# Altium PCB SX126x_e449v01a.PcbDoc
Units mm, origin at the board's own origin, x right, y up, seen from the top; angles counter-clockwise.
Board outline 89 x 58 mm, 4 copper layers (Top Layer, MidLayer1, MidLayer2, Bottom Layer), stack 0.986 mm thick; 79 components, 51 nets, 222 pads, 1241 vias.
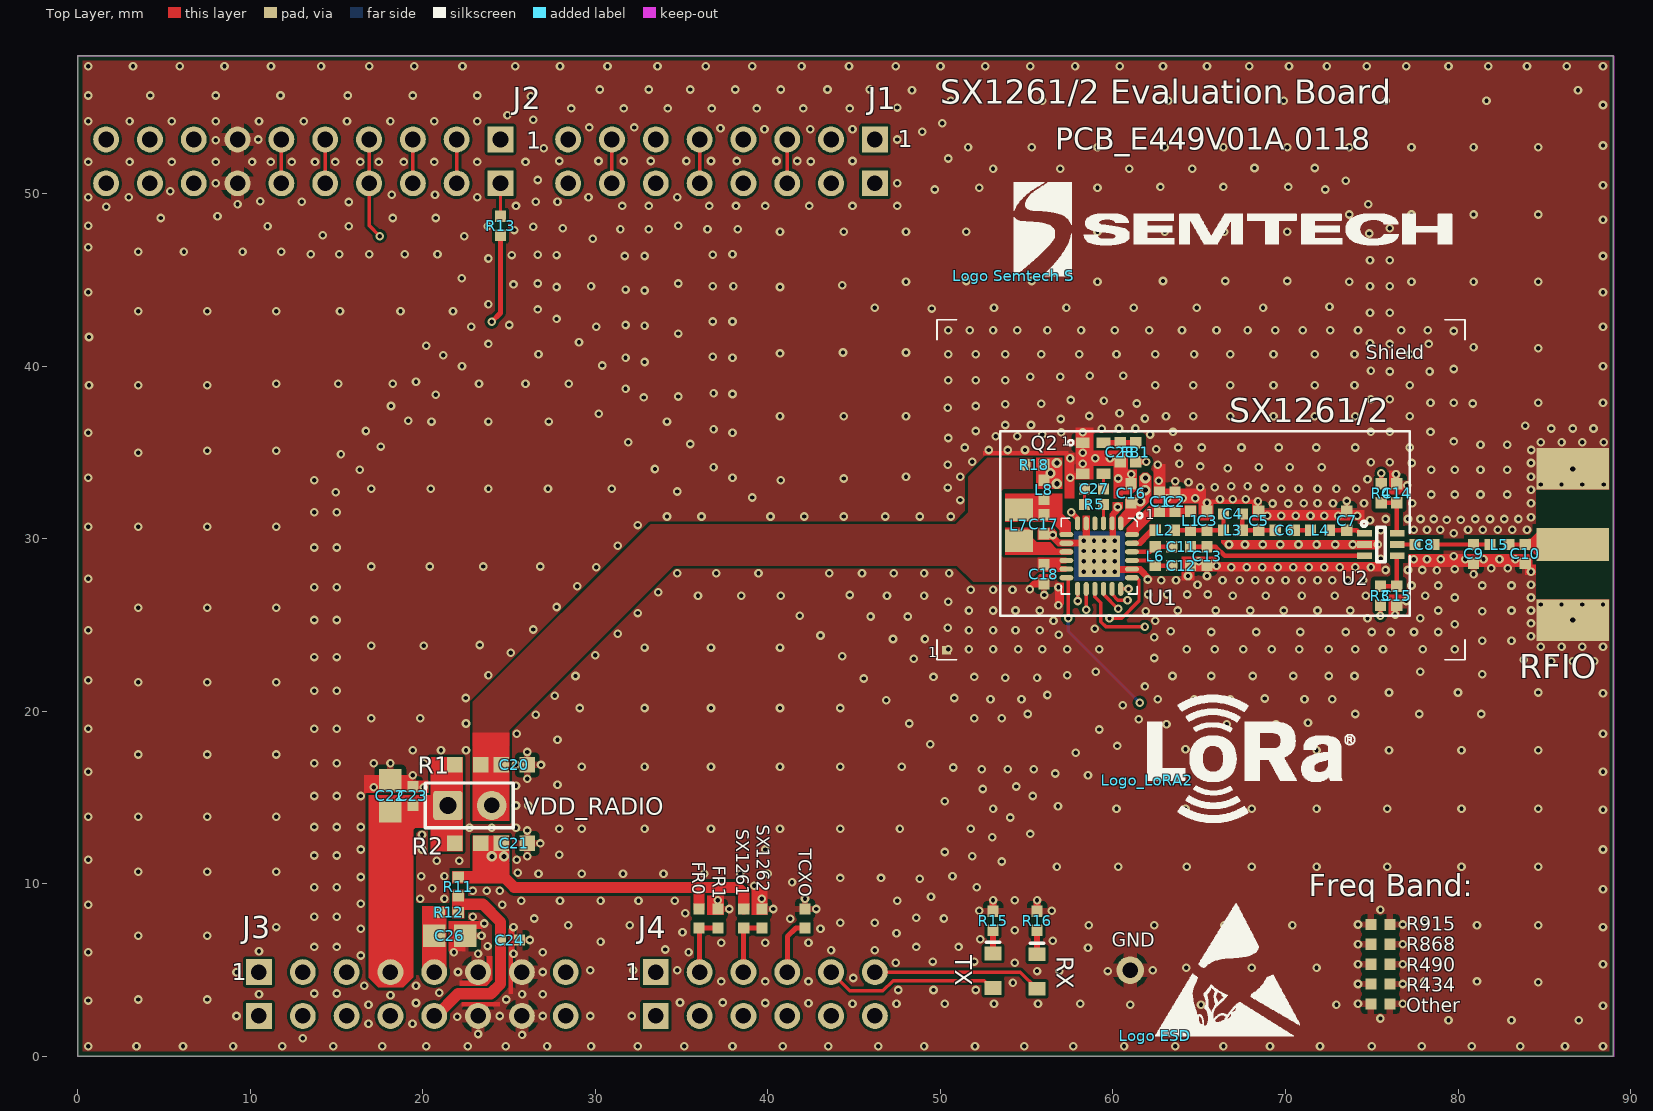
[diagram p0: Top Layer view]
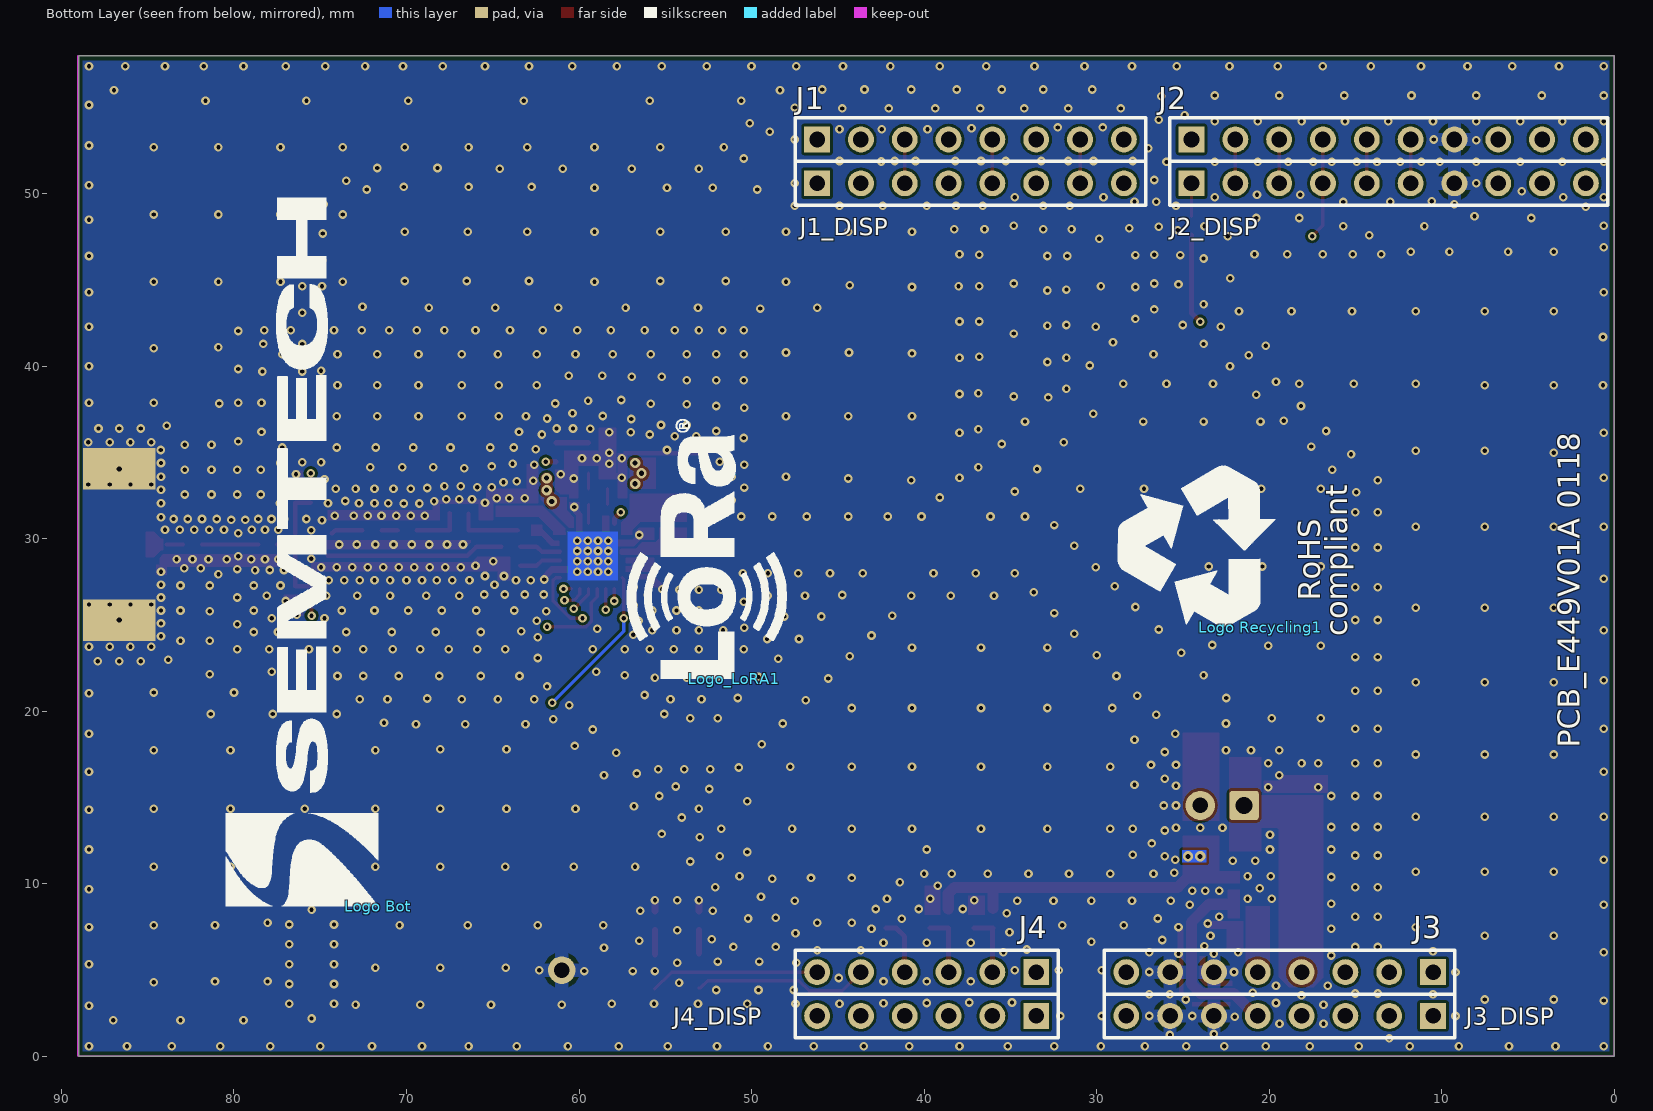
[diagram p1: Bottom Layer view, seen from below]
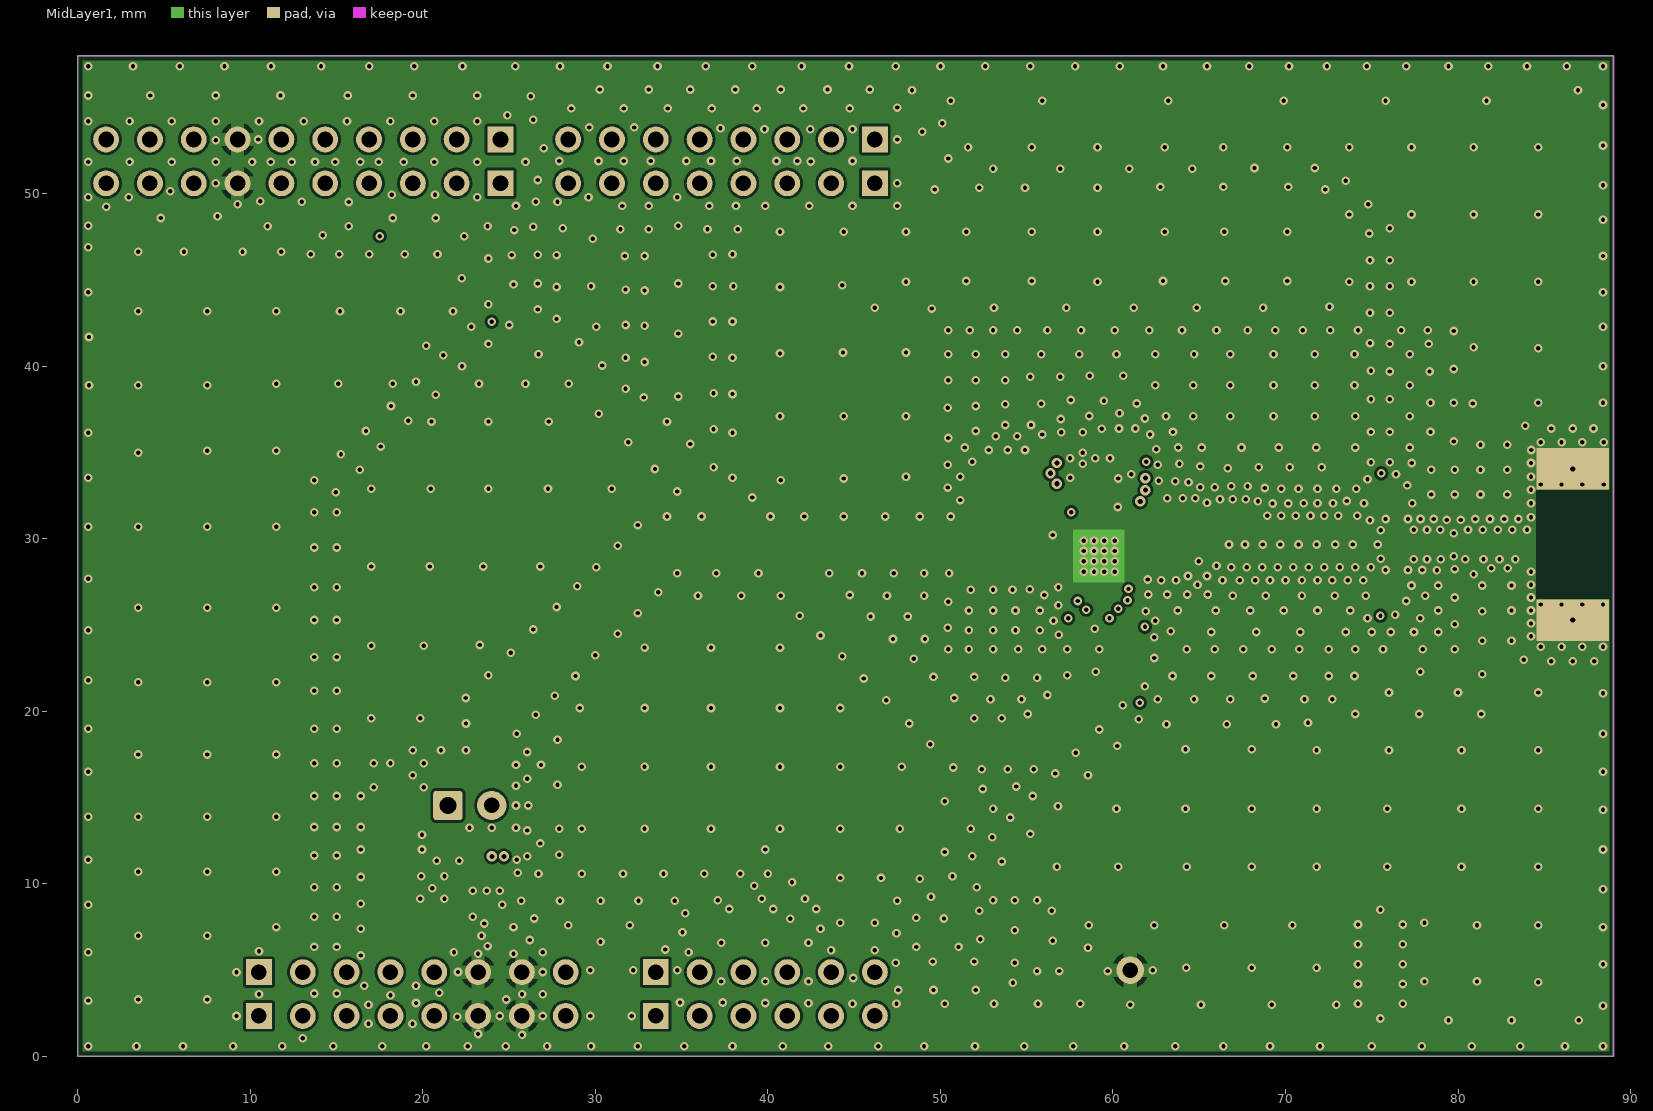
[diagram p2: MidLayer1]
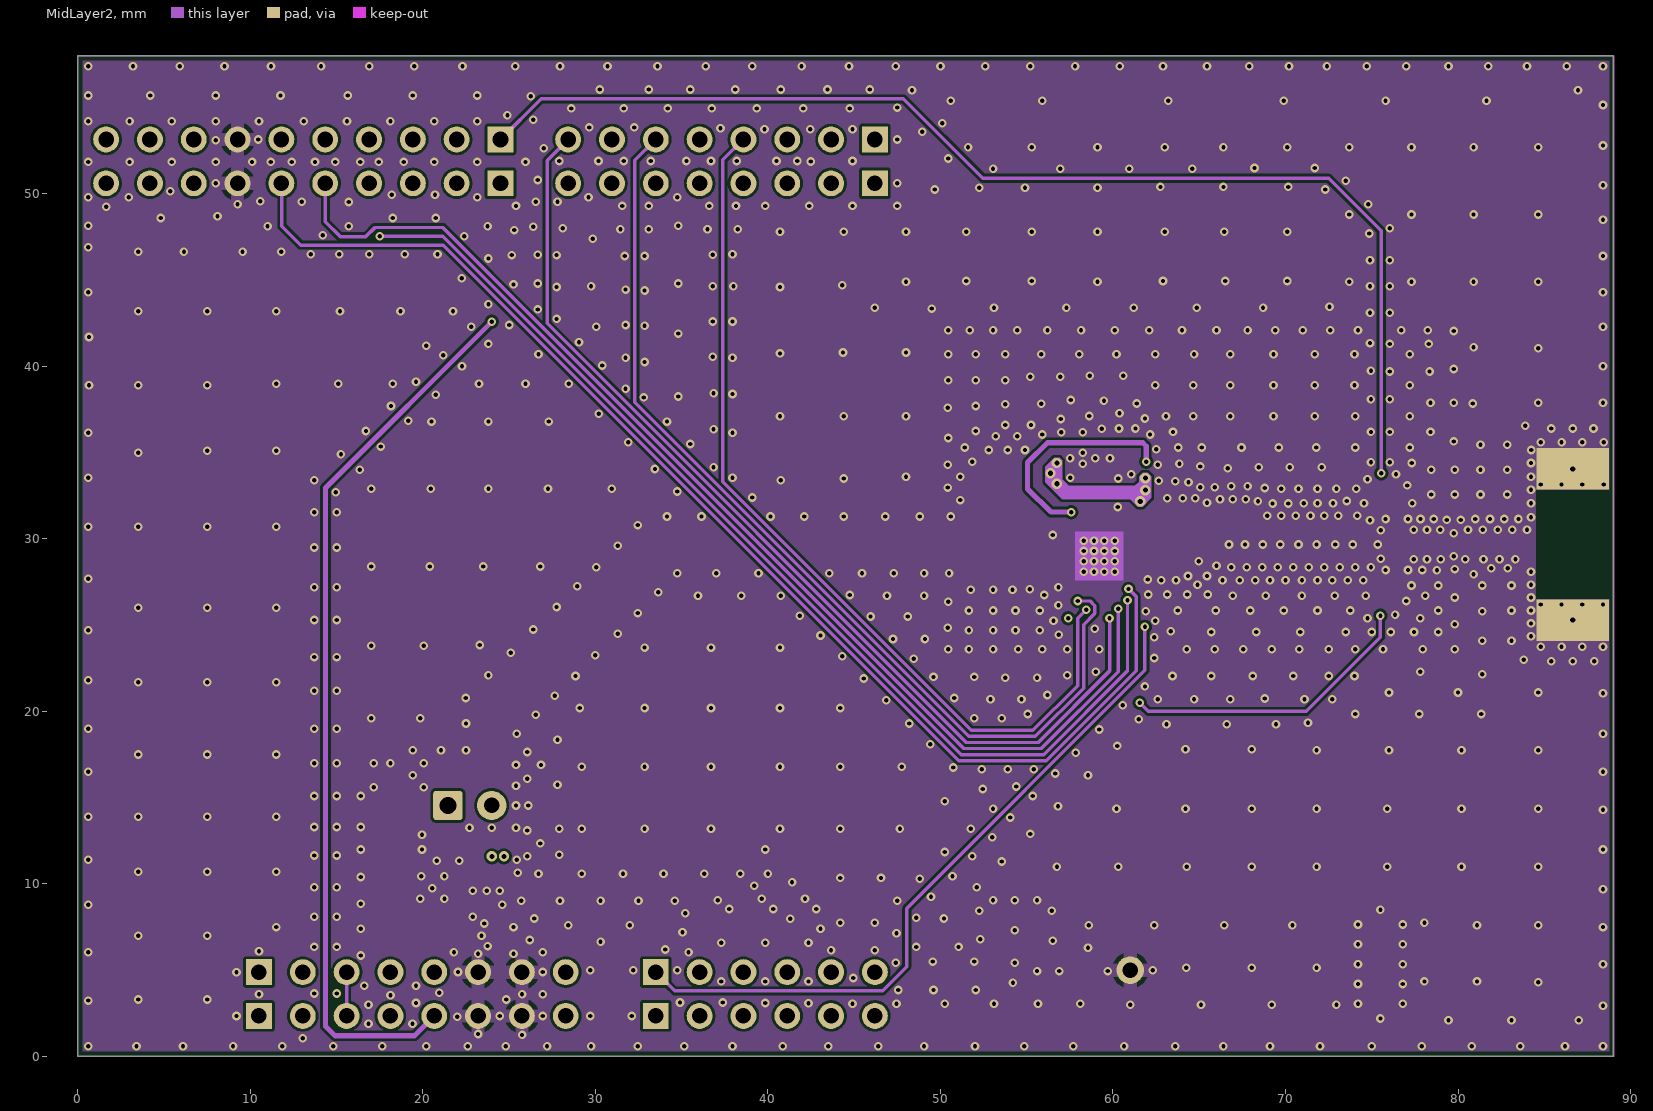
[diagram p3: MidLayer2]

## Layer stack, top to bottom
Top Solder: solder mask 0.0102, Solder Resist, Dk 3.5
Top Layer: signal copper 0.035
Dielectric1: core 0.15, FR-4, Dk 4.4
MidLayer1: signal copper 0.018
Dielectric3: prepreg 0.58, FR-4, Dk 4.4
MidLayer2: signal copper 0.018
Dielectric2: core 0.15, FR-4, Dk 4.4
Bottom Layer: signal copper 0.035
Bottom Solder: solder mask 0.0102, Solder Resist, Dk 3.5

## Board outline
0,0 0,58 89,58 89,0

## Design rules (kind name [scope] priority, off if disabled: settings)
Clearance Clearance_RF_GND [InNet('GND') And OnLayer('Top Layer') And (InPoly) vs InNet('NetL*') or InNet('NetC*') or InNet('NetU*')] p1: gap=0.25 ignorepadtopadclearanceinfootprint=FALSE except(0: Arc-Hole Track-Hole SMDPad-Hole THPad-Hole Via-Hole Fill-Hole Poly-Hole Region-Hole Text-Hole)
Clearance Clearance_GND_Keepout [InNet('GND') vs OnLayer('Keep-Out Layer')] p2: gap=0.15 ignorepadtopadclearanceinfootprint=FALSE except(0: Arc-Hole Track-Hole SMDPad-Hole THPad-Hole Via-Hole Fill-Hole Poly-Hole Region-Hole Text-Hole)
Clearance Clearance_GND [InNet('GND')] p3: gap=0.15 ignorepadtopadclearanceinfootprint=FALSE except(0: Arc-Hole Track-Hole SMDPad-Hole THPad-Hole Via-Hole Fill-Hole Poly-Hole Region-Hole Text-Hole)
Clearance [All] p4: gap=0.15 ignorepadtopadclearanceinfootprint=FALSE except(0: Arc-Hole Track-Hole SMDPad-Hole THPad-Hole Via-Hole Fill-Hole Poly-Hole Region-Hole Text-Hole)
ComponentClearance ComponentClearance_SMA_RFIO [InComponent('RFIO')] p1: gap=0.1 collisioncheckmode=3 verticalgap=0.1 showdistances=FALSE
ComponentClearance [All] p2: gap=0.2 collisioncheckmode=3 verticalgap=0.3 showdistances=FALSE
HoleSize [All] p1: absolutevalues=TRUE maxlimit=3.6 minlimit=0.25 maxpercent=80.000 minpercent=20.000
HoleToHoleClearance [All] p1: gap=0.2 allowstackedmicrovias=TRUE
MinimumSolderMaskSliver [All] p1: minsoldermaskwidth=0.04
PlaneClearance [All] p1: clearance=0.2
PlaneConnect [All] p1: planeconnectstyle=Direct reliefexpansion=0.508 reliefentries=4 reliefconductorwidth=0.254 reliefairgap=0.254
PolygonConnect "PolygonConnect SMD" [InNet('GND') vs HasFootprint('rlc_603_smd') or HasFootprint('rlc_402_smd') or hasFootprint('rlc_805_smd')  or hasFootprint('SOT353-5') or hasFootprint('VQFN24_4X4MM')   or hasFootprint('TCXO 2.0x1.6mm')  or HasFootprint('ND2016DA')  or HasFootprint('DFN6_3X3mm')   or HasFootprint('ODFN6_1.65X1.65mm')] p1: connectstyle=Relief reliefconductorwidth=0.4 reliefentries=4 polygonreliefangle="90 Angle" airgapwidth=0.254
PolygonConnect PolygonConnect_comp_diverse [InNet('GND') or  InNet('VDD_MBED') or  InNet('VDD_DISPLAY')  or  InNet('VDD_3V3')  or  InNet('VDD_RADIO')  or  InNet('VUSB') vs HasFootprint('LGM676 LED') or  HasFootprint('BRIDGE_254MM') or  HasFootprint('pin_0.9mm') or HasFootprint('SMA_STRAIGHT')  or  HasFootprint('HDR2X8')   or  HasFootprint('HDR2X6')  or  HasFootprint('HDR1X10') or  HasFootprint('vqfn20_3x3mm') or  HasFootprint('HDR1X9') or  HasFootprint('HDR1X8')  or  HasFootprint('HDR1X6') or  HasFootprint('HDR1X4')] p2: connectstyle=Relief reliefconductorwidth=0.8 reliefentries=4 polygonreliefangle="90 Angle" airgapwidth=0.254
PolygonConnect PolygonConnect_all [All] p3: connectstyle=Direct reliefconductorwidth=0.6 reliefentries=4 polygonreliefangle="90 Angle" airgapwidth=0.254
RoomDefinition SX126x_e449v01a [InComponentClass('SX126x_e449v01a')] p1: confinementstyle=ConfineOut formatcopy=TRUE lockcomponents=FALSE outline 13.5,81.35 13.45,81.4 13.45,124.35 67.45,124.35 67.3,124.2 67.3,81.35
RoutingVias [All] p1: holewidth=0.3 width=0.6 viastyle="Through Hole" minholewidth=0.25 minwidth=0.5 maxholewidth=0.4 maxwidth=0.8
SilkToSilkClearance [All] p1: silktosilkclearance=0.05
SilkToSolderMaskClearance SilkscreenOverComponentPads [IsPad] p1: minsilkscreentomaskgap=0.05 clearancetoexposedcopper=TRUE
SolderMaskExpansion [All] p1: expansion=0.05
Width "Width GND" [InNet('GND')] p1: maxlimit=3 minlimit=0.2 preferedwidth=0.4
Width Width_VCC [InNet('VDD') or  InNet('VDISPLAY') or  InNet('VDD_MBED')  or  InNet('VUSB')  or  InNet('VDD_3V3')] p2: maxlimit=2 minlimit=0.2 preferedwidth=0.8
Width "Width All" [All] p3: maxlimit=2 minlimit=0.15 preferedwidth=0.2
22 further rules are at their usual default settings.

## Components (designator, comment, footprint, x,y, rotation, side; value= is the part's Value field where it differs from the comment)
C1 "Cap" RLC_402_SMD 62.7,32.15 r270 top value=NC
C2 "Cap" RLC_402_SMD 63.6,32.15 r270 top value=NC
C3 "Cap" RLC_402_SMD 65.45,31.05 r270 top value=NC
C4 "Cap" RLC_402_SMD 66.95,31.45 r180 top value=NC
C5 "Cap" RLC_402_SMD 68.45,31.05 r270 top value=NC
C6 "Cap" RLC_402_SMD 69.95,30.5 r180 top value=NC
C7 "Cap" RLC_402_SMD 73.55,31.05 r270 top value=NC
C8 "Cap" RLC_402_SMD 78.05,29.675 r180 top value=NC
C9 "Cap" RLC_402_SMD 80.9,29.125 r90 top value=NC
C10 "Cap" RLC_402_SMD 83.9,29.125 r90 top value=NC
C11 "Cap" RLC_402_SMD 63.95,29.55 r180 top value=NC
C12 "Cap" RLC_402_SMD 63.95,28.45 r180 top value=NC
C13 "Cap" RLC_402_SMD 65.45,29 r90 top value=NC
C14 "Cap" RLC_402_SMD 76.45,32.65 r90 top value=1nF
C15 "Cap" RLC_402_SMD 76.45,26.7 r270 top value=1nF
C16 "Cap" RLC_402_SMD 61.05,32.65 r270 top value=1uF
C17 "Cap" RLC_402_SMD 56,30.85 r90 top value=470nF
C18 "Cap" RLC_402_SMD 56,27.95 r90 top value=100nF
C20 "Cap" rlc_603_smd 25.3,16.9 r180 top value=1uF
C21 "Cap" rlc_603_smd 25.3,12.35 r180 top value=1uF
C22 "Cap" rlc_805_smd 18.12,15.1 r270 top value=10uF
C23 "Cap" RLC_402_SMD 19.42,15.1 r270 top value=100nF
C24 "Cap" RLC_402_SMD 25.05,6.75 r180 top value=1uF
C26 "Cap" rlc_805_smd 21.55,7 r180 top value=10uF
C27 "Cap" RLC_402_SMD 58.9,32.9 r180 top value=15pF
C28 "Cap" RLC_402_SMD 60.425,35.025 r90 top value=100nF
FB1 "Ferrite beads" RLC_402_SMD 61.325,35.025 r90 top value=NC
FR0 "Resistor" RLC_402_SMD 36,8 r270 top value=1k
FR1 "Resistor" RLC_402_SMD 37.1,8 r270 top value=NC
GND "Test Pin" pin_0.9mm 61,5 r90 top
J1 "Header 8" HDR1X8 46.2,53.15 r180 bottom locked
J1_DISP "Header 8" HDR1X8 46.2,50.61 r180 bottom locked
J2 "Header 10" HDR1X10 24.5,53.15 r180 bottom locked
J2_DISP "Header 10" HDR1X10 24.5,50.61 r180 bottom locked
J3 "Header 8" HDR1X8 10.5,4.89 r0 bottom locked
J3_DISP "Header 8" HDR1X8 10.5,2.35 r0 bottom locked
J4 "Header 6" HDR1X6 33.5,4.89 r0 bottom locked
J4_DISP "Header 6" HDR1X6 33.5,2.35 r0 bottom locked
L1 "Inductor" RLC_402_SMD 64.5,31.05 r90 top value=0R
L2 "Inductor" RLC_402_SMD 63,30.5 r0 top value=0R
L3 "Inductor" RLC_402_SMD 66.95,30.5 r0 top value=0R
L4 "Inductor" RLC_402_SMD 72,30.5 r0 top value=0R
L5 "Inductor" RLC_402_SMD 82.4,29.675 r0 top value=0R
L6 "Inductor" RLC_402_SMD 62.45,29 r90 top value=0R
L7 "Inductor" "rlc_805_smd enlarged" 54.55,30.8 r270 top value=15uH
L8 "Inductor" rlc_402_smd 56,32.85 r270 top value=47nH
"Logo Bot" "Logo symbol" logo_semtech_horiz_size4 71.65,8.7 r90 bottom
"Logo ESD" "Logo symbol" "Logo ESD" 62.454,1.2 r0 top
"Logo Recycling1" "Logo symbol" "Logo Recycling1" 20.527,24.87 r90 bottom
"Logo Semtech S" "Logo symbol" logo_semtech_horiz_size3 54.25,45.25 r0 top
Logo_LoRA1 "Logo symbol" "LOGO LORA SIZE4" 51,21.9 r90 bottom
Logo_LoRA2 "Logo symbol" "LOGO LORA SIZE3" 62,16 r0 top
Other "Resistor" RLC_402_SMD 75.5,3.05 r0 top value=NC
Q2 "TCXO" "TCXO 2.0x1.6mm" 58.85,34.675 r270 top value=32.0MHz
R1 "Resistor" rlc_603_smd 22.6,16.9 r180 top value=NC
R2 "Resistor" rlc_603_smd 22.6,12.35 r180 top value=0R
R3 "Resistor" RLC_402_SMD 75.5,26.7 r270 top value=100R
R4 "Resistor" RLC_402_SMD 75.55,32.65 r90 top value=100R
R5 "Resistor" rlc_402_smd 58.9,32 r180 top value=?
R11 "Resistor" RLC_402_SMD 22.05,9.85 r270 top value=NC
R12 "Resistor" RLC_402_SMD 21.5,8.35 r0 top value=0R
R13 "Resistor" RLC_402_SMD 24.5,48.15 r90 top value=10k
R15 "Resistor" RLC_402_SMD 53.05,7.871 r270 top value=330R
R16 "Resistor" RLC_402_SMD 55.6,7.871 r270 top value=330R
R18 "Resistor" rlc_402_smd 55.45,34.3 r180 top value=0R
R434 "Resistor" RLC_402_SMD 75.5,4.2 r0 top value=NC
R490 "Resistor" rlc_402_smd 75.5,5.35 r180 top value=NC
R868 "Resistor" RLC_402_SMD 75.5,6.5 r0 top value=NC
R915 "Resistor" RLC_402_SMD 75.5,7.65 r180 top value=NC
RFIO "SMA" SMA_end_launch_1.0mm_9.52mm 86.65,29.675 r0 top locked
RX "LED" "LGM676 LED" 55.6,4.921 r90 top value=GREEN
Shield "Logo symbol" "BMIS-209-F - Shield - Solder_Mask" 50.35,23.55 r0 top locked
SX1261 "Resistor" rlc_402_smd 38.6,8 r270 top value=NC
SX1262 "Resistor" RLC_402_SMD 39.65,8 r270 top value=10k
TCXO "Resistor" rlc_402_smd 42.15,8 r270 top value=NC
TX "LED" "LGM676 LED" 53.05,4.971 r90 top value=RED
U1 "SX1261/2" VQFN24_4X4MM 59.2,29 r270 top
U2 "PE4259 RF Switch" SC70-6 75.525,29.675 r0 top
VDD_RADIO "Jumper" BRIDGE_254MM 21.45,14.55 r0 top

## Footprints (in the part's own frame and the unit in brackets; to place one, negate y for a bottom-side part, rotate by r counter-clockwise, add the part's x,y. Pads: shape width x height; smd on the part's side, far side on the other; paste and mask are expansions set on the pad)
"BMIS-209-F - Shield - Solder_Mask" [mm] "BMIS-209-F EMI Gasket - modif SolderMask - Standard Surface Mount Shields -  Laird Technologies"
  rect 0.5x0.5 smd paste-1 mask+0.05: 1(0,0)
  Mechanical 15 keep-out lines w1: 0,0 0,18.6 29.5,18.6 29.5,0 0,0
  silkscreen extent -0.55,-0.55 30.05,19.15, body extent -0.3,-0.3 0.3,0.3, height 0.8
BRIDGE_254MM [mm] "Generic Bridge 2.54mm, 2 Leads 0.9mm;"
  rrect20% 1.7x1.7 hole 1 paste+0 mask+0.05: 1(0,0)
  round 1.7 hole 0.9 paste+0 mask+0.05: 2(2.54,0)
  silkscreen extent -1.3,-1.3 3.8,1.3, body extent -1.4,-1.4 3.9,1.4, height 1
HDR1X6 [mm] "Connector; Header; 6 Position"
  rect 1.5x1.5 hole 0.9: 1(0,0)
  round 1.5 hole 0.9: 2(2.54,0) 3(5.08,0) 4(7.62,0) 5(10.16,0) 6(12.7,0)
  silkscreen extent -1.27,-1.27 13.97,1.27, body extent -0.8,-0.8 13.5,0.8
HDR1X8 [mm] "Connector; Header; 8 Position"
  rect 1.5x1.5 hole 0.9: 1(0,0)
  round 1.5 hole 0.9: 2(2.54,0) 3(5.08,0) 4(7.62,0) 5(10.16,0) 6(12.7,0) 7(15.24,0) 8(17.78,0)
  silkscreen extent -1.27,-1.27 19.05,1.27, body extent -0.8,-0.8 18.58,0.8
HDR1X10 [mm] "Connector; Header; 10 Position"
  rect 1.5x1.5 hole 0.9: 1(0,0)
  round 1.5 hole 0.9: 2(2.54,0) 3(5.08,0) 4(7.62,0) 5(10.16,0) 6(12.7,0) 7(15.24,0) 8(17.78,0) 9(20.32,0) 10(22.86,0)
  silkscreen extent -1.27,-1.27 24.13,1.27, body extent -0.8,-0.8 23.66,0.8
"LGM676 LED" [mm] "Chip Diode; Body 2.1 x 1.4 mm (LxW typ)"
  rect 0.8x1 smd mask+0.05: 1(-1,0) 2(1,0)
  silkscreen extent 1.65,-0.4 1.65,0.4, body extent -1.2,-0.7 1.2,0.7, height 12
"Logo ESD" [mm] "Logo ESD"
  silkscreen extent 0,0 8.38,7.67
"LOGO LORA SIZE3" [mm] "Logo LoRa Size3 - Top Overlay - 14.5x8mm - Registered"
  silkscreen extent 0,-2.44 12.03,4.96, body extent 2.3,-0.1 5.25,2.65, height 0.8
"LOGO LORA SIZE4" [mm] "Logo LoRa Size4 - Top Overlay - 18x9.5mm - Registered"
  silkscreen extent 0,-3.05 15.04,6.2
"Logo Recycling1" [mm] "Logo Recycling1"
  silkscreen extent 0.05,-0.88 9.36,8.2
logo_semtech_horiz_size3 [mm] "Logo semtech horizontal - size3 - L"
  silkscreen extent 0,0 25.4,5.41
logo_semtech_horiz_size4 [mm] "Logo semtech horizontal - size4 - XL"
  silkscreen extent 0,0 41.07,8.79
pin_0.9mm [mm] "Generic Pin 0.9mm; 1 Lead"
  round 1.6 hole 0.9 mask+0.05: 1(0,0)
RLC_402_SMD [mm] "Chip SMD component 402; Body 1.0 x 0.5 mm (LxW typ)"
  rect 0.65x0.65 smd mask+0.05: 1(-0.55,0) 2(0.55,0)
  body extent -0.87,-0.33 0.87,0.33, height 0.8
rlc_402_smd [mm] "Chip SMD component 402; Body 1.0 x 0.5 mm (LxW typ)"
  rect 0.65x0.65 smd mask+0.05: 1(-0.55,0) 2(0.55,0)
  body extent -0.87,-0.33 0.87,0.33, height 0.8
rlc_603_smd [mm] "Chip SMD component 603; Body 1.6 x 0.8mm (LxW typ)"
  rect 0.9x0.9 smd paste+0 mask+0.05: 1(-0.75,0) 2(0.75,0)
rlc_805_smd [mm] "Chip SMD component 805; Body 2.0 x 1.25 mm (LxW typ)"
  rect 1.3x1.3 smd mask+0.05: 1(-0.9,0) 2(0.9,0)
"rlc_805_smd enlarged" [mm] "Chip SMD component 805; Body 2.0 x 1.25 mm (LxW typ)"
  rect 1.3x1.6 smd mask+0.05: 1(-0.9,0) 2(0.9,0)
SC70-6 [mm] "SC70 6-Leads, Body 2.0x1.25mm, Pitch 0.65mm"
  rect 0.85x0.4 smd mask+0.05: 1(-0.95,0.65) 2(-0.95,0) 3(-0.95,-0.65) 4(0.95,-0.65) 5(0.95,0) 6(0.95,0.65)
  silkscreen extent -1.12,-1 0.25,1.35, body extent -0.63,-1 0.63,1, height 1.45
SMA_end_launch_1.0mm_9.52mm [mm] "SMA end launch for 1.0mm PCB thickness; 9.52mm"
  rect 4.2x1.905 smd mask+0.05: 1(0,0)
  rect 4.2x2.413 hole 0.3 mask+0.05: 2(0,-4.38) 2(0,4.38)
"TCXO 2.0x1.6mm" [mm] "SMD 2.0x1.6mm for TCXO or VCTCXO"
  rect 0.6x0.8 smd mask+0.05: 1(-0.9,-0.6) 2(0.9,-0.6) 3(0.9,0.6) 4(-0.9,0.6)
  silkscreen extent -1.05,-1.45 -0.75,-1.15, body extent -1,-0.8 1,0.8, height 1
VQFN24_4X4MM [mm] "24 Leads, Body 4.0x4.0mm, Pitch 0.50mm, VQFN24"
  oval 0.8x0.3 smd mask+0.05: 1(-1.9,1.25) 2(-1.9,0.75) 3(-1.9,0.25) 4(-1.9,-0.25) 5(-1.9,-0.75) 6(-1.9,-1.25) 13(1.9,-1.25) 14(1.9,-0.75) 15(1.9,-0.25) 16(1.9,0.25) 17(1.9,0.75) 18(1.9,1.25)
  oval 0.3x0.8 smd mask+0.05: 7(-1.25,-1.9) 8(-0.75,-1.9) 9(-0.25,-1.9) 10(0.25,-1.9) 11(0.75,-1.9) 12(1.25,-1.9) 19(1.25,1.9) 20(0.75,1.9) 21(0.25,1.9) 22(-0.25,1.9) 23(-0.75,1.9) 24(-1.25,1.9)
  rrect5% 2.4x2.4 smd paste-2.5 mask+0.05: 25(0,0)
  Mechanical 15 keep-out lines w0.1: 2.5,-2.5 2.5,2.5 -2.5,2.5 -2.5,-2.5 2.5,-2.5
  silkscreen extent -2.5,-2.2 2.2,2.5, body extent -2,-2 2,2, height 1

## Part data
C1 C2 C3 C4 C5 C6 C7 C8 C9 C10 C11 C12 C13 C14 C15 C16 C17 C18 C20 C21 C22 C23 C24 C26 C27 C28: "Capacitor SMD"
FR0 FR1 Other R1 R2 R3 R4 R5 R11 R12 R13 R15 R16 R18 R434 R490 R868 R915 SX1261 SX1262 TCXO: "Resistor SMD - IEC symbol version"
GND: library part test_pin
J1 J1_DISP J3 J3_DISP: "Header, 8-Pin"
J2 J2_DISP: "Header, 10-Pin"
J4 J4_DISP: "Header, 6-Pin"
L1 L2 L3 L4 L5 L6 L7 L8: "Inductor SMD"
"Logo Bot" "Logo ESD" "Logo Recycling1" "Logo Semtech S" Logo_LoRA1 Logo_LoRA2: library part Logo, "Schematic symbol for Logo"
RFIO: "SMA Straight Connector"
Shield: library part Shield, "Shield - EMI Gasket - Standard Surface Mount Shields"
U1: library part SX126x, "SX1261/2 - Ultra low power RF transceiver"
U2: "PE4259 Peregrine RF Switch"
VDD_RADIO: "Jumper Wire"

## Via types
v1: diameter 0.5, hole 0.25, Top Layer to Bottom Layer, tented both sides, 1217 vias
v2: diameter 0.5, hole 0.25, Top Layer to Bottom Layer, tented top, 16 vias
v3: diameter 0.6, hole 0.3, Top Layer to Bottom Layer, tented both sides, 8 vias

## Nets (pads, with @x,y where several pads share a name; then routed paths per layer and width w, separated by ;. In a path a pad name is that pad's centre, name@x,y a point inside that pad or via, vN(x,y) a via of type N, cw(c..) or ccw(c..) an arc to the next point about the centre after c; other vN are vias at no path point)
ANT_SW: J2.1 R4.2 | length 69.8
  Top Layer w0.25: R4.2 v1(75.55,33.8)
  MidLayer2 w0.2: J2.1 26.85,55.5 47.85,55.5 52.45,50.9 72.5,50.9 75.55,47.85 v1(75.55,33.8)
BUSY: J1.4 U1.14 | length 53.7
  Top Layer w0.2: v1(58.45,25.9) U1.14
  MidLayer2 w0.2: J1.4@38.575,53.15 37.39,51.965 37.39,33.305 51.795,18.9 55.35,18.9 57.95,21.5 57.95,25.4 v1(58.45,25.9)
DIO1: J1.6 U1.13 | length 57.8
  Top Layer w0.2: v1(57.95,26.4) U1.13
  MidLayer2 w0.2: J1.6 32.286,51.936 32.286,37.914 51.65,18.55 55.5,18.55 58.3,21.35 58.3,25.025 58.95,25.675 58.95,26.125 58.675,26.4 v1(57.95,26.4)
DIO2: R3.2 U1.12 | length 26.8
  Top Layer w0.2: v1(57.4,25.4) 57.4,27.65 U1.12@57.5,27.75
  Top Layer w0.25: v1(75.5,25.55) R3.2
  MidLayer2 w0.2: v1(61.55,20.5) 62.05,20 71.199,20 75.5,24.301 v1(75.5,25.55)
  Bottom Layer w0.2: v1(57.4,25.4) 57.399,24.651 v1(61.55,20.5)
DIO3: FB1.1 U1.6 | length 14.3
  Top Layer w0.3: v1(57.575,31.55) 57.95,31.175 U1.6 ; FB1.1 v1(61.925,34.475)
  MidLayer2 w0.3: v1(57.575,31.55) 56.4,31.55 55.05,32.9 55.05,34.425 56.2,35.575 61.725,35.575 61.925,35.375 v1(61.925,34.475)
DISP_RESET: J3.3 J3_DISP.3 | length 2.5
  Top Layer w0.3: J3.3@15.58,4.87 J3.3@15.6,4.89
  MidLayer2 w0.2: J3_DISP.3 J3.3@15.58,4.87
F_CS: J1.7 J1_DISP.7 | length 2.6
  Top Layer w0.2: J1.7@30.95,53.175 30.96,53.165 J1.7 J1_DISP.7
GND: C1.1 C2.1 C3.1 C5.1 C7.1 C9.1 C10.1 C12.1 C13.1 C14.2 C15.2 C16.1 C17.1 C18.1 C20.1 C21.1 C22.1 C23.1 C24.1 C26.1 C28.1 FR1.1 GND.1 J2.7 J2_DISP.7 J3.6 J3.7 J3_DISP.6 J3_DISP.7 Other.1 Other.2 Q2.1 Q2.2 R15.1 R16.1 R434.1 R434.2 R490.1 R490.2 R868.1 R868.2 R915.1 R915.2 RFIO.2 Shield.1 SX1262.1 TCXO.1 U1.2 U1.5 U1.8 U1.20 U1.25 U2.2 | length 5.3
  Top Layer w0.3: U1.8 U1.25@58.3,29.75 ; U1.25@58.45,29.85 U1.5 ; U1.25@59.95,29.9 U1.2 ; U1.25@60.1,28.2 60.15,28.25 U1.20 ; C16.1@61.012,33.2 C16.1
  Top Layer w0.4: R15.1 v1@53.05,9.021 ; R16.1 v1(55.6,9.05)
  other v1: 0.6,0.6 3.4,0.6 6.1,0.6 9,0.6 11.85,0.6 14.8,0.6 17.65,0.6 20.2,0.6 22.6,0.6 24.8,0.6 27.2,0.6 29.75,0.6 32.45,0.6 35.15,0.6 37.95,0.6 40.85,0.6 43.5,0.6 46.4,0.6 49.05,0.6 52,0.6 54.85,0.6 57.7,0.6 60.643,0.6 63.6,0.6 66.4,0.6 69.1,0.6 72,0.6 75,0.6 77.9,0.6 80.8,0.6 83.6,0.6 86.2,0.6 88.4,0.6 13.04,1.05 25.75,1.25 23.2,1.3 16.85,1.9 19.4,1.9 79.45,2.1 83.1,2.1 87,2.1 75.5,2.2 22,2.3 9.2,2.35 24.45,2.35 26.95,2.35 29.7,2.35 32.1,2.35 88.4,2.938 16.85,3 61,3 65.1,3 69.2,3 72.95,3 44.9,3.05 47.45,3.05 50.25,3.05 53.1,3.05 55.65,3.05 58.1,3.05 74.2,3.05 76.8,3.05 19.6,3.1 39.85,3.1 42.35,3.088 34.9,3.13 37.39,3.13 0.6,3.241 3.5,3.3 7.5,3.3 24.829,3.3 18.125,3.55 10.5,3.6 25.75,3.6 26.95,3.6 13.7,3.65 15,3.65 20.95,3.7 47.55,3.85 49.6,3.85 52.05,3.85 16.6,4.1 19.6,4.1 74.2,4.2 76.8,4.2 54.2,4.279 84.65,4.3 37.3,4.35 39.85,4.35 42.35,4.35 78.05,4.35 81.1,4.35 44.95,4.55 9.2,4.89 22.035,4.9 26.95,4.9 55.6,4.95 56.886,4.95 59.7,4.95 29.7,5 32.2,5 34.75,5 62.3,5 64.25,5.15 68.05,5.15 71.8,5.15 88.4,5.338 74.2,5.35 76.8,5.35 47.4,5.435 54.3,5.435 49.55,5.5 51.95,5.5 16.4,5.85 23.2,5.95 25.25,5.95 0.6,6.05 21.8,6.05 26.95,6.05 35.4,6.05 10.5,6.1 43.66,6.15 46.2,6.15 34.046,6.2 58.55,6.3 13.7,6.35 15,6.35 48.6,6.35 51.05,6.35 23.75,6.4 74.2,6.5 76.8,6.5 37.3,6.6 39.85,6.6 42.35,6.6 30.3,6.65 56.5,6.7 26.2,6.75 52.3,6.8 3.5,7 7.5,7 23.4,7 47.45,7.15 35.05,7.2 54.3,7.321 16.4,7.4 43.05,7.4 11.5,7.5 25.25,7.5 88.4,7.5 28.42,7.6 32,7.6 58.6,7.6 62.4,7.6 66.45,7.6 70.4,7.6 81.1,7.6 84.65,7.6 74.2,7.65 76.8,7.65 23.55,7.709 44.2,7.75 46.2,7.75 78.05,7.75 41.3,7.975 26.45,8 50.2,8 48.6,8.05 13.7,8.1 15,8.1 22.9,8.1 35.2,8.3 52.25,8.45 56.45,8.45 75.5,8.5 37.75,8.55 40.3,8.55 42.8,8.55 0.6,8.8 24.6,8.8 16.4,8.85 25.7,9.021 27.95,9.021 30.3,9.021 32.5,9.021 34.6,9.021 47.5,9.021 37.1,9.05 53.05,9.05 54.3,9.05 19.85,9.15 21.25,9.15 39.65,9.15 42.15,9.15 49.45,9.25 22.9,9.6 23.7,9.6 24.45,9.6 88.4,9.7 20.55,9.75 13.7,9.8 15,9.8 52.1,9.8 39.2,9.9 41.4,10.1 48.8,10.3 44.2,10.35 46.55,10.35 16.4,10.4 19.9,10.45 21.25,10.45 50.7,10.45 26.7,10.6 29.2,10.6 31.6,10.6 33.95,10.6 36.3,10.6 38.4,10.6 40,10.6 25.5,10.65 3.5,10.7 7.5,10.7 11.5,10.7 56.75,11 60.3,11 64.275,11 68.05,11 71.8,11 75.9,11 80.2,11 84.65,11 53.55,11.3 20.8,11.35 22.1,11.35 0.6,11.4 25.45,11.4 26.05,11.6 51.85,11.6 13.7,11.65 15,11.65 27.9,11.7 50.25,11.85 16.4,12 19.95,12 39.85,12 88.4,12 26.8,12.35 53,12.7 19.95,12.85 55.2,12.9 26.05,13.1 27.9,13.2 29.2,13.2 32.85,13.2 36.7,13.2 40.7,13.2 44.2,13.2 47.65,13.2 51.75,13.2 22.7,13.25 24,13.25 25.4,13.25 13.7,13.3 15,13.3 16.4,13.3 54.05,13.85 0.6,13.9 3.5,13.9 7.5,13.9 11.5,13.9 88.4,14.3 53.05,14.35 60.2,14.35 64.2,14.35 68.05,14.35 71.8,14.35 75.9,14.35 80.2,14.35 84.65,14.35 56.81,14.5 25.4,14.55 26.1,14.55 50.25,14.8 13.7,15.1 15,15.1 16.4,15.1 55.35,15.1 52.45,15.5 17.15,15.6 20.05,15.6 54.4,15.65 25.4,15.7 27.8,15.75 26.05,16.1 19.42,16.3 58.55,16.3 56.65,16.4 0.6,16.5 88.4,16.5 52.4,16.65 53.9,16.65 55.4,16.65 50.75,16.75 29.2,16.8 32.85,16.8 36.7,16.8 40.7,16.8 44.2,16.8 47.75,16.8 25.4,16.9 26.85,16.9 13.7,17 15,17 17.15,17 18.12,17 20.05,17 3.5,17.5 7.5,17.5 11.5,17.5 57.85,17.6 26.05,17.65 19.42,17.75 21.05,17.75 22.5,17.75 71.8,17.75 76,17.75 80.2,17.75 84.65,17.75 64.2,17.8 68.05,17.8 60.25,18 49.4,18.1 27.8,18.35 25.45,18.7 88.4,18.7 59.2,18.95 0.6,19 13.7,19 15,19 63.1,19.25 66.6,19.25 69.45,19.25 22.5,19.3 48.2,19.3 71.3,19.35 61.5,19.55 17,19.6 19.85,19.6 51.95,19.6 53.55,19.6 26.55,19.8 55.056,19.85 74.05,19.85 77.75,19.85 81.35,19.85 29.1,20.2 32.85,20.2 36.7,20.2 40.7,20.2 44.2,20.2 60.574,20.35 46.85,20.65 52.9,20.7 54.7,20.7 62.6,20.7 64.7,20.7 66.8,20.7 71.1,20.7 72.7,20.7 68.8,20.75 22.477,20.78 50.8,20.78 27.65,20.9 56.2,20.95 88.4,21.05 76,21.1 80,21.1 84.65,21.1 13.7,21.2 15,21.2 61.85,21.45 3.5,21.7 7.5,21.7 11.5,21.7 0.6,21.8 45.55,21.907 53.75,21.95 55.6,21.95 49.6,22 51.95,22 28.85,22.05 63.45,22.05 65.7,22.05 68.1,22.05 70.45,22.05 72.5,22.05 74,22.05 23.8,22.1 57.35,22.1 81.4,22.15 59,22.3 77.8,22.3 85.4,22.9 86.65,22.9 87.9,22.9 83.8,23 48.45,23.05 62.4,23.1 13.7,23.15 15,23.15 44.3,23.2 30,23.25 25.1,23.4 50.45,23.6 51.65,23.6 53.05,23.6 54.5,23.6 55.9,23.6 57.35,23.6 59.2,23.6 64.275,23.6 65.9,23.6 67.55,23.6 69.2,23.6 70.8,23.6 72.5,23.6 74.05,23.6 75.65,23.6 77.95,23.6 79.8,23.6 32.85,23.7 36.7,23.7 40.7,23.7 84.8,23.75 86,23.75 87.2,23.75 88.4,23.75 17,23.8 20.05,23.8 23.3,23.85 81.4,24.1 83.1,24.1 47.25,24.2 49.1,24.2 62.4,24.3 84.225,24.35 43.05,24.4 56.85,24.45 31.3,24.5 65.7,24.6 68.3,24.6 70.85,24.6 73.5,24.6 75,24.6 76.1,24.6 77.45,24.6 78.85,24.6 63.35,24.65 0.6,24.7 51.65,24.7 53.05,24.7 54.35,24.7 55.75,24.7 26.4,24.75 58.95,24.8 50.425,24.85 79.8,25.05 84.225,25.1 56.55,25.25 62.45,25.25 13.7,25.3 15,25.3 74.75,25.4 77.8,25.4 45.95,25.5 48.1,25.5 41.85,25.55 76.35,25.6 32.45,25.7 61.9,25.8 81.4,25.8 51.65,25.85 53.05,25.85 54.35,25.85 55.75,25.85 63.75,25.85 65.95,25.85 67.95,25.85 69.9,25.85 71.85,25.85 73.75,25.85 78.85,25.85 83.1,25.85 84.225,25.85 3.5,26 7.5,26 11.5,26 27.75,26.05 56.837,26.15 84.8,26.2 86,26.2 87.2,26.2 88.4,26.2 50.45,26.35 77,26.4 79.8,26.6 84.225,26.6 35.95,26.7 38.45,26.7 40.75,26.7 46.9,26.7 49.05,26.7 66.95,26.7 68.85,26.7 70.95,26.7 72.85,26.7 74.65,26.7 78.1,26.7 44.75,26.75 56.011,26.75 62.05,26.775 63.15,26.775 64.3,26.775 65.5,26.775 33.65,26.9 51.75,27.05 53.05,27.05 54.175,27.05 55.175,27.075 13.7,27.2 15,27.2 56.837,27.2 28.95,27.25 77.3,27.3 78.85,27.3 81.4,27.3 83.1,27.3 64.9,27.35 84.225,27.35 62.8,27.6 63.65,27.6 66.35,27.6 67.35,27.6 68.25,27.6 69.1,27.6 70,27.6 70.95,27.6 71.85,27.6 72.7,27.6 73.6,27.6 74.5,27.6 62.016,27.65 0.6,27.696 64.35,27.85 65.45,27.85 80.9,27.95 34.75,28 37,28 39.45,28 43.55,28 45.45,28 47.3,28 49.05,28 50.5,28 84.225,28.1 78.775,28.175 75.8,28.2 77.1,28.2 77.925,28.2 79.8,28.25 81.925,28.3 82.875,28.3 30.05,28.35 66.85,28.35 67.75,28.35 68.65,28.35 69.55,28.35 70.45,28.35 71.35,28.35 72.25,28.35 73.15,28.35 74.05,28.35 74.95,28.35 17,28.4 20.4,28.4 23.5,28.4 26.8,28.4 66,28.45 64.975,28.7 77.425,28.825 78.2,28.825 79,28.825 80.425,28.825 81.475,28.825 82.4,28.825 83.325,28.825 75.525,28.85 79.75,29 13.7,29.5 15,29.5 31.3,29.6 66.725,29.675 67.65,29.675 68.675,29.675 69.7,29.675 70.75,29.675 71.8,29.675 72.875,29.675 73.9,29.675 75.35,29.675 56.5,30.225 79.75,30.325 75.525,30.5 77.425,30.525 78.2,30.525 78.975,30.525 80.575,30.525 81.425,30.525 82.3,30.525 83.15,30.525 84,30.525 0.6,30.7 3.5,30.7 7.5,30.7 11.5,30.7 32.45,30.8 74.9,31.075 79.35,31.1 80.15,31.1 75.8,31.15 77.1,31.15 77.825,31.15 78.6,31.15 81,31.15 81.85,31.15 82.675,31.15 83.5,31.15 84.225,31.25 34.15,31.3 36.15,31.3 40.15,31.3 42.1,31.3 44.4,31.3 46.8,31.3 48.8,31.3 50.6,31.3 68.95,31.35 69.75,31.35 70.6,31.35 71.45,31.35 72.25,31.35 73.05,31.35 74.15,31.35 13.7,31.55 15,31.55 60.275,31.85 69.25,32.05 70.15,32.05 71.05,32.075 71.85,32.075 72.75,32.075 74.55,32.075 77.35,32.075 84.225,32.075 65.45,32.1 68.4,32.175 73.55,32.2 51.15,32.25 66.2,32.3 66.95,32.3 67.7,32.3 63.15,32.35 64.05,32.35 64.775,32.35 39.1,32.4 78.45,32.575 79.8,32.575 81.3,32.575 82.85,32.575 14.955,32.7 34.75,32.75 84.225,32.85 17,32.9 20.45,32.9 23.8,32.9 27.25,32.9 30.95,32.9 69.75,32.9 70.75,32.9 71.85,32.9 72.95,32.9 74.1,32.9 68.8,32.95 50.425,32.975 65.05,33 65.9,33 66.85,33.05 67.8,33.05 77.05,33.1 84.8,33.15 86,33.15 87.2,33.15 88.45,33.15 64.375,33.28 63.6,33.35 62.65,33.375 13.7,33.4 40.75,33.4 74.75,33.45 44.4,33.5 60.3,33.5 0.6,33.55 37.95,33.55 57.525,33.55 48,33.6 51.15,33.6 84.225,33.6 61.05,33.75 76.4,33.75 16.35,34 78.45,34 79.8,34 81.3,34 82.85,34 33.45,34.05 66.65,34.1 36.85,34.15 68.45,34.15 70.25,34.15 72.1,34.15 65.05,34.2 50.425,34.3 62.6,34.3 58.25,34.35 63.85,34.35 77.325,34.4 84.225,34.4 74.95,34.45 76.05,34.45 51.85,34.475 57.512,34.675 58.975,34.675 59.825,34.675 15.25,34.9 3.5,35 58.25,35 7.5,35.1 11.5,35.1 52.8,35.15 53.9,35.15 54.9,35.15 84.25,35.15 62.5,35.2 51.4,35.3 63.775,35.3 65.15,35.3 67.45,35.3 69.6,35.3 71.775,35.3 74.05,35.3 77.2,35.3 17.55,35.35 81.3,35.45 82.85,35.45 35.5,35.5 31.9,35.6 84.8,35.6 86,35.6 87.2,35.6 88.45,35.6 79.75,35.65 50.45,35.85 53.2,35.95 54.45,35.95 55.9,36.05 62.15,36.05 0.6,36.15 37.95,36.15 57,36.175 58.25,36.175 63.475,36.2 74.95,36.2 76.05,36.2 78.4,36.2 16.7,36.25 52.05,36.25 36.85,36.35 59.35,36.375 60.35,36.4 61.3,36.4 85.4,36.4 86.65,36.4 87.85,36.4 83.9,36.55 53.75,36.6 55.25,36.6 20.5,36.8 23.8,36.8 27.3,36.8 34.15,36.8 19.15,36.85 56.975,36.95 61.85,36.975 40.7,37.1 44.4,37.1 48,37.1 63.075,37.1 64.65,37.1 66.8,37.1 69.3,37.1 71.7,37.1 74.05,37.1 77.2,37.1 58.625,37.125 30.2,37.25 60.375,37.275 50.425,37.6 18.15,37.7 52.05,37.7 53.75,37.8 55.84,37.825 61.375,37.85 80.85,37.85 78.4,37.9 79.75,37.9 84.65,37.9 88.4,37.9 59.475,38 57.55,38.05 74.95,38.1 76.05,38.1 32.8,38.2 34.8,38.25 20.75,38.35 37.95,38.4 36.85,38.45 31.75,38.7 0.65,38.9 3.5,38.9 7.5,38.9 62.45,38.9 64.65,38.9 66.8,38.9 69.3,38.9 71.7,38.9 74,38.9 77.2,38.9 11.5,39 15.1,39 18.25,39 23.25,39 25.95,39 28.45,39 19.6,39.1 50.45,39.2 52.05,39.2 53.75,39.2 55.2,39.4 56.95,39.4 58.65,39.45 60.6,39.45 76.05,39.7 78.35,39.7 74.95,39.75 79.75,39.85 22.265,40 88.4,40 30.4,40.05 32.85,40.25 31.75,40.5 37.95,40.5 36.8,40.55 21.183,40.65 26.7,40.7 50.45,40.7 52.05,40.7 53.75,40.7 55.85,40.7 58.05,40.7 60.2,40.7 62.45,40.7 64.7,40.7 66.8,40.7 69.3,40.7 71.7,40.7 74,40.7 77.2,40.7 40.7,40.75 44.35,40.8 48,40.8 84.65,41.05 80.9,41.1 20.2,41.2 23.8,41.3 76.05,41.3 78.3,41.3 74.9,41.35 29.05,41.4 0.65,41.7 34.8,41.9 79.75,42.05 50.45,42.1 51.7,42.1 53.05,42.1 54.45,42.1 56.2,42.1 58.15,42.1 60.1,42.1 62.1,42.1 64,42.1 66,42.1 67.8,42.1 69.4,42.1 71,42.1 72.6,42.1 74.2,42.1 76.7,42.1 78.25,42.1 22.8,42.3 30.05,42.3 88.4,42.3 32.85,42.35 25,42.4 31.75,42.4 36.8,42.6 37.95,42.6 27.75,42.75 74.9,43.1 76.05,43.1 3.5,43.2 7.5,43.2 11.5,43.2 15.2,43.2 18.7,43.2 21.75,43.2 26.65,43.3 49.5,43.35 46.2,43.4 53.1,43.4 57.3,43.4 61.2,43.4 64.85,43.4 68.7,43.4 72.55,43.45 23.8,43.6 0.6,44.3 88.4,44.3 32.85,44.4 31.75,44.45 27.75,44.6 40.7,44.6 29.75,44.65 36.8,44.65 38,44.65 74.9,44.65 76.05,44.65 44.3,44.7 25.25,44.75 26.65,44.8 34.8,44.8 48,44.9 59.1,44.9 73.7,44.9 77.3,44.9 80.9,44.9 84.65,44.9 51.5,44.95 55.291,44.95 62.9,44.95 66.5,44.95 70.1,44.95 22.25,45.1 74.9,46.15 76.05,46.15 23.8,46.25 31.7,46.4 32.85,46.4 88.4,46.4 25.15,46.45 27.75,46.45 26.65,46.464 36.8,46.464 13.5,46.5 15.15,46.5 16.9,46.5 18.95,46.5 20.85,46.5 37.95,46.5 3.5,46.65 6.15,46.65 9.55,46.65 11.8,46.65 0.6,46.9 29.85,47.4 22.4,47.546 14.2,47.6 74.85,47.7 40.7,47.8 44.4,47.8 48,47.8 51.5,47.8 55.3,47.8 59.1,47.8 63,47.8 66.45,47.8 70.1,47.8 25.3,47.9 31.45,47.95 33.1,47.95 36.5,47.95 38.25,47.95 28.1,48 76.05,48 26.4,48.1 11,48.125 15.7,48.125 23.75,48.125 0.6,48.15 34.8,48.15 88.4,48.5 4.8,48.6 18.25,48.6 20.75,48.6 8.1,48.7 73.7,48.8 77.3,48.8 80.9,48.8 84.65,48.8 1.65,49.25 25.4,49.3 31.55,49.3 33.1,49.3 36.6,49.3 38.15,49.3 39.85,49.3 42.4,49.3 44.9,49.3 47.5,49.3 9.26,49.4 74.8,49.4 15.7,49.525 12.975,49.55 26.55,49.55 27.8,49.55 10.575,49.575 0.6,49.803 2.95,49.803 23.15,49.803 29.6,49.8 34.75,49.8 18.2,49.95 20.7,49.95 5.35,50.15 49.675,50.25 72.3,50.25 52.25,50.35 54.9,50.35 59.1,50.35 62.75,50.4 66.4,50.4 70.15,50.4 88.4,50.5 8,50.61 47.5,50.61 73.5,50.75 26.65,50.8 53.05,51.45 56.95,51.45 60.95,51.45 64.6,51.45 68.2,51.5 71.7,51.5 0.6,51.85 3,51.85 5.45,51.85 8,51.85 10.1,51.85 11.175,51.85 12.4,51.85 13.75,51.85 14.925,51.85 16.375,51.85 17.45,51.85 18.9,51.85 20.66,51.85 23.15,51.85 25.95,51.85 42.475,51.875 27.9,51.9 30.18,51.9 31.65,51.9 33.2,51.9 35.275,51.9 36.7,51.9 38.2,51.9 40.5,51.9 41.7,51.9 44.9,51.9 50.45,52.05 27,52.65 51.6,52.7 55.3,52.7 59.1,52.7 63,52.7 66.4,52.7 70.1,52.7 73.7,52.7 77.3,52.7 80.9,52.7 84.65,52.7 88.4,52.8 8,53.1 10.45,53.15 47.5,53.15 48.95,53.6 39.8,53.75 42.45,53.75 44.9,53.75 37.25,53.8 29.65,53.85 32.25,53.85 50.1,54.1 0.6,54.2 3,54.2 5.45,54.2 8,54.2 10.5,54.2 13.1,54.2 15.6,54.2 18.12,54.2 20.66,54.2 23.15,54.2 26.4,54.3 24.9,54.55 28.6,54.95 31.65,54.95 34.2,54.95 36.75,54.95 39.35,54.95 42.05,54.95 44.75,54.95 47.5,55 88.4,55.15 50.6,55.4 55.9,55.4 63.2,55.4 69.9,55.4 75.8,55.4 81.65,55.4 26.25,55.65 0.6,55.7 4.2,55.7 8,55.7 11.75,55.7 15.65,55.7 19.42,55.7 23.15,55.7 48.35,56 86.95,56 30.25,56.05 33.1,56.05 35.5,56.05 38.1,56.05 40.75,56.05 43.45,56.05 45.9,56.05 0.6,57.4 3.2,57.4 5.9,57.4 8.5,57.4 11.2,57.4 14.1,57.4 16.9,57.4 19.501,57.4 22.3,57.4 25.35,57.4 27.95,57.4 30.7,57.4 33.6,57.4 36.4,57.4 39.1,57.4 41.95,57.4 44.7,57.4 47.4,57.4 50,57.4 52.6,57.4 55.2,57.4 57.802,57.4 60.4,57.4 62.9,57.4 65.45,57.4 67.9,57.4 70.2,57.4 72.4,57.4 74.7,57.4 77,57.4 79.45,57.4 81.75,57.4 84,57.4 86.3,57.4 88.4,57.4
  other v2: 58.3,28.1 58.9,28.1 59.5,28.1 60.1,28.1 58.3,28.7 58.9,28.7 59.5,28.7 60.1,28.7 58.3,29.3 58.9,29.3 59.5,29.3 60.1,29.3 58.3,29.9 58.9,29.9 59.5,29.9 60.1,29.9
LED_RX: J4.6 RX.1 | length 9.8
  Top Layer w0.2: J4.6 54.631,4.89 RX.1
LED_TX: J4.5 TX.1 | length 10.3
  Top Layer w0.2: J4.5 44.75,3.8 46.656,3.8 47.256,4.4 52.55,4.4 52.979,3.971 TX.1
MISO: J2.5 J2_DISP.5 U1.16 | length 70.9
  Top Layer w0.2: J2.5@14.325,53.2 14.34,53.185 J2.5 J2_DISP.5 ; U1.16 59.45,26.784 v1@60.284,25.95
  MidLayer2 w0.2: J2_DISP.5@14.35,50.625 14.35,48.375 15.2,47.525 16.7,47.525 17.225,48.05 21.148,48.05 51.348,17.85 55.84,17.85 60.3,22.31 v1(60.3,25.95)
MOSI: J2.4 J2_DISP.4 U1.17 | length 69.1
  Top Layer w0.2: J2.4@16.875,53.185 16.88,53.18 J2.4 J2_DISP.4 16.88,48.174 v1(17.504,47.55) ; U1.17 59.95,26.784 60.284,26.45 v1(60.841,26.45)
  MidLayer2 w0.2: v1(17.504,47.55) 21.153,47.55 51.203,17.5 55.985,17.5 60.841,22.356 v1(60.841,26.45)
NetC3_2: C3.2 C4.2 L1.1 L2.2 L3.1 | length 3.8
  Top Layer w0.25: L2.2 L1.1 C3.2 L3.1 C4.2
NetC4_1: C4.1 C5.2 C6.2 L3.2 | length 2.9
  Top Layer w0.25: C4.1@67.5,31.5 C4.1 L3.2 C5.2 C6.2
NetC6_1: C6.1 L4.1 | length 1
  Top Layer w0.25: C6.1 L4.1@71.45,30.5
NetC7_2: C7.2 L4.2 U2.1 | length 1.9
  Top Layer w0.25: L4.2 C7.2 74.125,30.5 74.3,30.325 U2.1@74.35,30.325
NetC8_1: C8.1 C9.2 L5.1 | length 3.3
  Top Layer w0.25: C8.1 C9.2 L5.1
NetC8_2: C8.2 U2.5 | length 1
  Top Layer w0.25: U2.5 C8.2
NetC10_2: C10.2 L5.2 RFIO.1 | length 1
  Top Layer w0.25: L5.2 C10.2
NetC11_1: C11.1 C13.2 U2.3 | length 10.3
  Top Layer w0.25: C11.1 C13.2 65.95,29.55 66.475,29.025 U2.3
NetC11_2: C11.2 L6.2 U1.22 | length 2.4
  Top Layer w0.25: U1.22 62.15,29.25 L6.2 C11.2
NetC12_2: C12.2 L6.1 U1.21 | length 2.4
  Top Layer w0.25: U1.21 62.15,28.75 L6.1 C12.2
NetC14_1: C14.1 R4.1 U2.6 | length 2.7
  Top Layer w0.25: R4.1 C14.1 U2.6@76.45,30.325
NetC15_1: C15.1 R3.1 U2.4 | length 2.7
  Top Layer w0.25: R3.1 C15.1 U2.4@76.45,29.025
NetC16_2: C16.2 L8.1 R18.1 U1.1
  other v3: 61.575,32.175 61.875,32.825 56.75,33.2 61.875,33.525 56.375,33.8 56.75,34.4
NetC17_2: C17.2 L7.1 L8.2 U1.7
NetC27_1: C27.1 Q2.3 | length 0.9
  Top Layer w0.2: C27.1 Q2.3@59.45,33.8
NetC27_2: C27.2 R5.2 | length 0.9
  Top Layer w0.2: R5.2 C27.2
NetC28_2: C28.2 FB1.2 Q2.4 | length 1.9
  Top Layer w0.3: Q2.4 C28.2 FB1.2
NetFR0_2: FR0.2 FR1.2 J4.2 | length 3.7
  Top Layer w0.3: J4.2@36,4.94 J4.2@36.04,4.9 ; J4.2 J4.2@36.04,4.9 ; J4.2@36.05,4.89 J4.2@36.04,4.9 ; FR1.2 FR0.2 36.04,7.41 J4.2@36.04,4.9
NetJ4_3: J4.3 SX1261.2 SX1262.2 | length 3.7
  Top Layer w0.2: J4.3@38.5,4.95 J4.3@38.58,4.87
  Top Layer w0.3: J4.3 SX1261.2@38.58,7.45 ; SX1261.2 SX1262.2
NetL2_1: L2.1 U1.23
NetL7_2: L7.2 U1.9
NetR15_2: R15.2 TX.2 | length 1.4
  Top Layer w0.35: TX.2 R15.2
NetR16_2: R16.2 RX.2 | length 1.4
  Top Layer w0.35: RX.2 R16.2
NSS: J1.8 U1.19 | length 62.4
  Top Layer w0.2: v1(59.8,25.4) 60.498,25.4 61.507,26.409 61.507,27.593 61.35,27.75 U1.19
  MidLayer2 w0.2: J1.8 27.2,51.93 27.2,42.493 51.493,18.2 55.657,18.2 59.8,22.343 v1(59.8,25.4)
OPT: J4.4 TCXO.2 | length 3.3
  Top Layer w0.3: J4.4@41.125,4.89 41.125,6.95 41.625,7.45 TCXO.2 TCXO.2@42.2,7.45
SCK: J2.6 J2_DISP.6 U1.18 | length 74.9
  Top Layer w0.2: J2_DISP.6 J2.6 J2.6@11.8,53.175 ; U1.18 v1(60.9,27.1)
  MidLayer2 w0.2: J2_DISP.6@11.825,50.61 11.825,48.125 12.925,47.025 21.183,47.025 51.058,17.15 56.13,17.15 61.341,22.361 61.341,26.659 v1(60.9,27.1)
SD_CS: J2_DISP.1 R13.2 | length 1.9
  Top Layer w0.2: R13.2 J2_DISP.1 J2_DISP.1
SX_NRESET: J4.1 U1.15 | length 45.8
  Top Layer w0.2: U1.15 58.95,26.65 59.3,26.3 59.3,25.193 59.593,24.9 v1(61.85,24.9)
  MidLayer2 w0.2: J4.1 34.59,3.8 46.65,3.8 48.05,5.2 48.05,8.575 61.85,22.375 v1(61.85,24.9)
  Bottom Layer w0.2: J4.1@33.5,4.85 J4.1
T_CS: J1.5 J1_DISP.5 | length 2.5
  Top Layer w0.2: J1.5@36.025,53.15 36.04,53.135 J1_DISP.5
T_IRQ: J1.3 J1_DISP.3 | length 2.6
  Top Layer w0.2: J1_DISP.3 J1.3 J1.3@41.12,53.185
TFT_CS: J2.3 J2_DISP.3 | length 2.5
  Top Layer w0.2: J2_DISP.3 J2.3
TFT_D: J2.2 J2_DISP.2 | length 2.5
  Top Layer w0.2: J2_DISP.2 J2.2
VDD_3V3: C21.2 FR0.1 R2.1 R11.1 SX1261.1 | length 17.9
  Top Layer w0.65: v3@23.99,11.6 23.99,11.11 25.3,9.8 36,9.8 ; FR0.1@36,8.575 36,9.8 ; SX1261.1 38.6,9.45 38.25,9.8 36,9.8
  other v3: 24,11.6 24.7,11.6
VDD_MBED: C22.2 C23.2 J3.4 R1.2 R2.2 VDD_RADIO.1 | length 0
VDD_RADIO: C18.2 C20.2 R1.1 R18.2 U1.10 U1.11 VDD_RADIO.2
VDISPLAY: C24.2 J3_DISP.5 R11.2 R12.2 R13.1 | length 68.1
  Top Layer w0.3: v1(23.99,42.59) 24.5,43.1 R13.1
  Top Layer w0.65: J3_DISP.5 20.75,2.35 22.035,3.635 23.935,3.635 24.5,4.2 C24.2 24.499,7.801 23.475,8.825 22.075,8.825
  MidLayer2 w0.3: J3_DISP.5 19.51,1.2 14.9,1.2 14.35,1.75 14.35,32.95 v1(23.99,42.59)
VR_PA: C1.2 C2.2 L1.2 U1.24
VUSB: C26.2 J3.5 R12.1
XTA: R5.1 U1.3 | length 1.1
  Top Layer w0.2: U1.3 R5.1@59.45,31.975
pads on no net: J1.1 J1.2 J1_DISP.1 J1_DISP.2 J1_DISP.4 J1_DISP.6 J1_DISP.8 J2.8 J2.9 J2.10 J2_DISP.8 J2_DISP.9 J2_DISP.10 J3.1 J3.2 J3.8 J3_DISP.1 J3_DISP.2 J3_DISP.4 J3_DISP.8 J4_DISP.1 J4_DISP.2 J4_DISP.3 J4_DISP.4 J4_DISP.5 J4_DISP.6 U1.4

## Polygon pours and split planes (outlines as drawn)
GND on Top Layer "Bottom GND" (solid, pour order 7): 0.3,0.3 88.75,0.3 88.75,57.7 0.3,57.7
VDD_RADIO on Top Layer "Top Layer VDD_RADIO" (solid, pour order 6): 22.9,20.55 33.2,30.85 50.892,30.85 51.6,31.558 51.6,33.6 52.7,34.7 55.35,34.7 55.35,32.9 53.675,32.9 53.5,32.725 53.5,29.05 53.65,28.9 56,28.9 56,28.4 55.107,27.507 51.893,27.507 50.95,28.45 34.55,28.45 25,18.9 25,18 22.9,18
GND on MidLayer1 "GND midlayer1" (solid, pour order 9): 0.3,0.3 88.75,0.3 88.75,57.7 0.3,57.7
GND on Bottom Layer "Bottom GND" (solid, pour order 10): 0.3,0.3 88.75,0.3 88.75,57.7 0.3,57.7
GND on MidLayer2 "GND midlayer2" (solid, pour order 8): 0.3,0.3 88.75,0.3 88.75,57.7 0.3,57.7

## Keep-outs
Keep-Out Layer:
  lines w0.05: 0,0 89.05,0 89.05,58 0,58 0,0

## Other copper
Top Layer:
  region net GND: 52.475,34.85 57.4,34.85 57.4,35.075 52.475,35.075
  region net GND: 39.076,8.226 39.975,8.225 39.975,9.9 39.076,9.9
  region net GND: 57.2,34.975 57.2,32.351 57.75,32.35 57.75,34.975
  pour cut-out: 57.675,33.475 57.675,32.575 57.115,32.575 57.115,31.6 57.825,31.6 57.825,33.475
  region net GND: 58.55,35.098 59.851,35.1 60.85,35.1 60.85,34 61.375,34 61.375,32.85 61.1,32.575 60.596,32.575 60.574,32.552 60.574,32.35 60.05,32.35 60.05,34.25 58.55,34.25
  region net GND: 58.85,36.45 58.85,33.45 57.475,33.45 57.475,33.75 57.525,33.8 57.85,33.8 57.85,36.45
  region net NetC16_2: 55.55,34.7 55.55,32.9 57.05,32.9 57.05,34.7
  pour cut-out: 62.3,32.075 65.048,32.075 65.05,32.073 65.05,32.045 62.3,32.045
  pour cut-out: 65.902,28.649 66.5,28.649 66.5,28.727 65.902,28.727
  region net GND: 63.975,27.6 63.975,28.975 65.898,28.975 66.227,28.649 75.525,28.649 75.525,28.125 64.7,28.125 64.7,27.6
  region net NetC10_2: 84.1,30 84.225,30 84.625,30.4 85.1,30.4 85.1,28.95 84.625,28.95 84.225,29.35 84.1,29.35
  pour cut-out: 88.8,26.5 84.5,26.5 84.5,32.85 88.8,32.85
  pour cut-out: 61.758,27.4 61.758,27.792 61.5,28.05 61.5,27.45 61.55,27.4
  region net GND: 75.975,25.55 75.975,26.775 77.1,26.775 77.1,26.275 76.35,26.275 76.35,25.55
  region net GND: 77.15,29.1 84.05,29.1 84.05,28.375 77.15,28.375
  region net GND: 74.55,31.075 68.075,31.075 68.075,32.1 68.475,32.1 68.475,31.65 74.55,31.65
  region net GND: 65.825,31.075 65.825,32.025 68.45,32.025 68.45,32.273 64.975,32.273 64.975,31.075
  region net GND: 62.375,34.325 62.375,32.075 65.381,32.075 65.381,32.9 63.025,32.9 63.025,34.325
  region net GND: 66.268,29.925 66.268,29.764 66.631,29.401 75.425,29.401 75.425,29.925
  region net VR_PA: 61.5,30.25 61.5,30.425 62.35,31.275 64.825,31.275 64.825,31.925 62.1,31.925 60.8,30.625 60.8,30.4 60.775,30.375 60.775,30.25
  region net NetL2_1: 61.15,29.6 61.625,29.6 62.2,30.175 62.775,30.175 62.775,30.825 62.125,30.825 62.125,30.6 61.425,29.9 61.15,29.9
  region net GND: 25,7.504 25,5.9 25.3,5.9 25.3,7.5
  region net GND: 22.24,3.145 24.45,3.145 24.45,2.9 22.24,2.9
  region net GND: 57.15,27.45 57.15,26.205 56.995,26.05 56.65,26.05 56.65,27.45
  region net GND: 59.8,29.9 59.8,31.45 60,31.65 60,32.125 60.575,32.125 60.575,31.775 60.15,31.35 60.15,29.9
  region net GND: 60.1,28.4 61.635,28.4 62.305,27.73 62.305,27.625 61.908,27.625 61.483,28.05 60.1,28.05
  region net GND: 16.595,15.3 20.3,15.3 20.3,15.975 19.42,15.975 19.42,16.3 16.595,16.3
  region net VDD_RADIO: 22.9,18.75 25,18.75 25,13.65 22.9,13.65
  region net VDD_3V3: 22.9,10.1 22.9,12.8 25,12.8 25,10.1
  region net VDD_MBED: 22.3,17.35 22.3,11.9 20.45,11.9 20.45,13.25 19.55,13.25 19.25,12.95 19.25,15.15 20.45,15.15 20.45,17.35
  region net VDD_MBED: 17.4,4 18.85,4 19.45,4.6 19.45,15.15 16.85,15.15 16.85,4.55
  region net NetC16_2: 60.3,30.65 60.3,31.25 60.725,31.675 60.725,32.425 61.175,32.425 61.525,32.775 61.525,33.625 61.725,33.825 62.025,33.825 62.225,33.625 62.225,32.275 60.6,30.65
  region net GND: 55.65,30.65 55.65,29.95 56.425,29.95 56.8,29.575 58.3,29.575 58.3,29.95 56.925,29.95 56.75,30.125 56.75,30.425 56.525,30.65
  region net NetL7_2: 57.65,29.35 57.575,29.425 56.725,29.425 56.35,29.8 55.575,29.8 55.35,30.025 55.35,30.65 53.75,30.65 53.75,29.075 57.575,29.075 57.65,29.15
  region net NetC17_2: 53.75,32.625 57.05,32.625 57.05,31 53.75,31
  region net NetC17_2: 55.85,32.35 56.175,32.35 57.55,30.975 57.55,30.25 56.9,30.25 56.9,30.5 55.849,31.551
  pour cut-out: 60.586,27.675 60.542,27.675 57.8,27.675 57.802,27.544 60.586,27.544
  pour cut-out: 60.586,27.625 60.45,27.625 60.45,30.325 57.775,30.325 57.775,30.449 60.58,30.452 60.582,30.45
  pour cut-out: 57.925,30.425 57.925,27.65 57.775,27.65 57.775,30.425
  region net VDISPLAY: 21.7,9.65 21.7,8 22.4,8 22.4,9.65
  region net VUSB: 19.95,8.7 19.95,4.89 21.35,4.89 21.35,8.7
  region net GND: 21.5,7.85 21.5,6.1 22.45,6.1 22.45,7.4 23.45,7.4 23.45,7.85
  region net VDD_3V3: 21.7,10.75 21.7,10.05 25,10.05 25,10.75
  region net GND: 58.25,29.9 58.25,31.35 58.65,31.35 58.65,29.9
  pour cut-out: 21.474,8.875 21.549,8.95 21.549,10.876 21.55,10.9 22.8,10.901 22.8,10.8 21.65,10.8 21.65,8.8 19.55,8.8 19.55,8.875
  pour cut-out: 22.6,9.95 22.6,7.85 22.4,7.85 22.4,9.95
  region net GND: 22.15,4.11 23.69,4.11 24.02,4.44 24.02,5.8 23.711,5.8 23.711,4.379 22.15,4.379
  region net GND: 24.975,3.635 24.975,7.4 25.2,7.4 25.2,3.635
  region net VDD_RADIO: 55.65,28.1 57.3,28.1 57.3,28.4 57,28.4 56.95,28.45 56.95,28.55 57,28.6 57.3,28.6 57.3,28.9 55.65,28.9
  region net GND: 55.04,27.241 55.749,27.95 56.75,27.95 56.75,27.725 56.7,27.675 55.875,27.675 55.725,27.525 55.725,27.2 55.04,27.2
  region net GND: 76.025,33.95 76.55,33.95 76.55,33.2 77.05,33.2 77.05,32.575 76.025,32.575
  region net GND: 84.12,29.1 84.3,28.92 84.3,28.505 84.5,28.505 84.5,27.93 83.9,27.925 83.9,29.1
  region net GND: 36.475,9.325 36.475,8.225 37.425,8.225 37.425,9.325
  pour cut-out: 65.825,31.05 65.825,32.026 68.072,32.026 68.075,31.025 68.025,31.025 68.025,31.975 65.875,31.975 65.875,31.05
  pour cut-out: 68.025,31.075 74.15,31.075 74.153,31.072 74.153,30.825 74.117,30.825 74.117,31.025 74.05,31.025 68.025,31.025
  pour cut-out: 62.106,27.873 63.975,27.873 63.975,29.075 63.9,29.075 63.9,27.945 63.855,27.99 62.106,27.99
  pour cut-out: 66.175,29.925 75.147,29.925 75.15,29.922 75.15,29.978 66.178,29.978 66.175,29.975
  pour cut-out: 76.8,30.776 77.15,30.775 77.15,30.251 79.175,30.251 79.175,30.051 80.324,30.051 80.325,30.251 84.25,30.251 84.25,30.175 80.4,30.175 80.4,30 79.1,30 79.1,30.175 77.075,30.175 77.072,30.7 76.8,30.7
  pour cut-out: 76.75,28.574 77.15,28.574 77.15,29.098 79.17,29.1 79.17,29.3 80.296,29.3 80.3,29.1 84.298,29.1 84.299,29.175 80.425,29.175 80.425,29.35 79.1,29.35 79.1,29.2 77.05,29.2 77.05,28.7 76.75,28.7
  pour cut-out: 75.797,28.574 75.793,30.775 76.125,30.776 76.125,30.65 75.95,30.65 75.95,28.625 76.1,28.625 76.1,28.574
  pour cut-out: 84.299,30.225 84.299,30.875 84.525,30.875 84.525,30.805 84.375,30.805 84.375,30.225
MidLayer2:
  region net NetC16_2: 56.6,34.7 56.9,34.7 57.05,34.55 57.05,33.45 57.425,33.075 61.275,33.075 61.525,33.325 61.525,33.625 61.725,33.825 62.025,33.825 62.225,33.625 62.225,32.375 61.725,31.875 61.425,31.875 61,32.3 57.05,32.3 56.075,33.275 56.075,34.175
  pour cut-out: 88.8,26.5 84.5,26.5 84.5,32.85 88.8,32.85
  region net GND: 57.8,30.4 57.8,27.6 60.6,27.6 60.6,30.4
MidLayer1:
  pour cut-out: 88.8,26.5 84.5,26.5 84.5,32.85 88.8,32.85
  region net GND: 57.7,30.525 57.7,27.5 60.643,27.5 60.643,30.525
Bottom Layer:
  region net VDD_3V3: 23.65,11.95 23.65,11.25 25.029,11.25 25.029,11.95
  region net GND: 57.75,30.4 57.75,27.6 60.65,27.6 60.65,30.4

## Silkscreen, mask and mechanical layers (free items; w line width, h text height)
Top Overlay:
  lines w0.15: 77.2,29 77.2,25.55 53.475,25.55 53.475,36.25 77.2,36.25 77.2,30.35
  text "SX1261/2 Evaluation Board" at 50,55.225 h1.4
  text "J2" at 25.2,54.9 h1.27
  text "J1" at 45.8,54.9 h1.27
  text "1" at 47.511,52.71 h1
  text "1" at 26,52.61 h1
  text "PCB_E449V01A 0118" at 56.65,52.55 h1.27
  text "SX1261/2" at 66.75,36.75 h1.4
  text "Freq Band:" at 71.35,9.3 h1.27
  text "J3" at 9.524,6.85 h1.27
  text "J4" at 32.45,6.85 h1.27
  text "1" at 8.911,4.41 h1
  text "1" at 31.731,4.415 h1
Bottom Overlay:
  text "RoHS" at 16.594,26.42 h2.2 r270
  text "compliant" at 15.044,24.37 h2.2 r270
  text "PCB_E449V01A 0118" at 2,17.9 h1.27 r270
Bottom Solder:
  region: 57.9,30.3 57.9,27.7 60.5,27.7 60.5,30.3
Mechanical 3:
  text "Origin(0;0)" at -9.95,-2.35 h1
Mechanical 14:
  the board outline again, w0.05

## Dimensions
0,0 to 0,58 on Mechanical 3
0,0 to 89,0 on Mechanical 3
0,0 to 61,5 on Mechanical 3
0,0 to 61,5 on Mechanical 3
